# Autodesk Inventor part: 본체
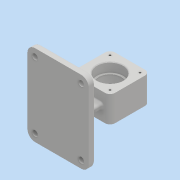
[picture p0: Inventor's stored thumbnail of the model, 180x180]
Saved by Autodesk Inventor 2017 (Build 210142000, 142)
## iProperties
Part Number: 본체
Material: 일반
Document SubType Name: Modeling
Designer: 222
Density: 1 g/cm^3
Appearance: 기본값
Author: 222
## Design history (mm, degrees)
sketch "스케치1"
  geometry: L1 (-32, -32)-(32, -32); L2 (32, -32)-(32, 32); L3 (32, 32)-(-32, 32); L4 (-32, 32)-(-32, -32); L5 (-32, -32)-(32, 32); L6 (32, -32)-(-32, 32); 1 further point
  constraints: 12 end point, 2 midpoint, 2 parallel, 1 horizontal, 1 perpendicular
  dimensions: "d0" = 64 distance of L3.end L2.end; "d1" = 64 distance of L2.end L1.end
extrude "돌출1" new body sketch "스케치1" stored distance "d2" = 42; taper "d3" = 0 deg
sketch "스케치2"
  geometry: C1 r 18 at (0, 0); 1 further point
  constraints: 1 centre point, 1 coincident
  dimensions: "d4" = 36 diameter of C1
extrude "돌출2" cut sketch "스케치2" stored distance "d5" = 42; taper "d6" = 0 deg
hole "구멍1" diameter "d9" = 42; stored, may be unused: countersink angle "d13" = 90 deg, drill point angle "d15" = 0 deg; dims "d7" = 10, "d8" = 10, "d10" = 6, "d11" = 4, "d12" = 2, "d14" = 15
hole "구멍2" diameter "d18" = 42; stored, may be unused: countersink angle "d22" = 90 deg, drill point angle "d24" = 0 deg; dims "d16" = 10, "d17" = 10, "d19" = 6, "d20" = 4, "d21" = 2, "d23" = 15
fillet "모깎기1" dims "d25" = 8
sketch "스케치3"
  geometry: L1 (-24, -24)-(24, -24); L2 (24, -24)-(24, 24); L3 (24, 24)-(-24, 24); L4 (-24, 24)-(-24, -24); L5 (-24, -24)-(24, 24); L6 (24, -24)-(-24, 24); 5 further points
  constraints: 12 end point, 4 coincident, 2 midpoint, 2 parallel, 1 horizontal, 1 perpendicular
  dimensions: "d26" = 48 distance of L3.end L2.end; "d27" = 48 distance of L2.end L1.end
hole "구멍3" sketch "스케치3" at (-24, 24), (24, 24), (-24, -24), (24, -24) diameter "d28" = 3.242; stored, may be unused: countersink angle "d32" = 90 deg, drill point angle "d34" = 118 deg; dims "d29" = 8, "d30" = 4, "d31" = 2, "d33" = 10
sketch "스케치4"
  geometry: L1 (-62, -60)-(36, -60); L2 (36, -60)-(36, -70); L3 (36, -70)-(-62, -70); L4 (-62, -70)-(-62, -60); 1 further point
  constraints: 8 end point, 2 parallel, 1 horizontal, 1 perpendicular
  dimensions: "d35" = 70 distance from line of L3 point (0, 0); "d36" = 10 distance of L1.end L2.end; "d37" = 98 distance of L2.end L3.end; "d38" = 62 distance from line of L4 point (0, 0)
extrude "돌출3" join sketch "스케치4" stored distance "d39" = 130; taper "d40" = 0 deg
sketch "스케치5"
  geometry: L1 (58, 48)-(66, 48); L2 (66, 48)-(66, 82); L3 (66, 82)-(58, 82); L4 (58, 82)-(58, 48); L5 (58, 48)-(66, 82); L6 (66, 48)-(58, 82); L7 (42, 61)-(82, 61); L8 (82, 61)-(82, 69); L9 (82, 69)-(42, 69); L10 (42, 69)-(42, 61); L11 (42, 61)-(82, 69); L12 (82, 61)-(42, 69); L13 (98, 130)-(0, 130) reference; L14 (0, 0)-(0, 130) reference; 4 further points
  constraints: 24 end point, 6 midpoint, 4 parallel, 2 horizontal, 2 perpendicular
  dimensions: "d45" = 8 distance of L3.end L2.end; "d46" = 34 distance of L2.end L1.end; "d47" = 40 distance of L9.end L8.end; "d48" = 8 distance of L8.end L7.end; "d49" = 65 distance from line of L13 point (62, 65); "d50" = 62 distance from line of L14 point (62, 65)
extrude "돌출4" join sketch "스케치5" stored distance "d51" = 130; taper "d52" = 0 deg
fillet "모깎기2" dims "d53" = 12, "d54" = 12
sketch "스케치6"
  geometry: L1 (0, -130)-(74, -130) reference; L2 (-12, -118)-(-12, -12) reference; L3 (74, 0)-(0, 0) reference; L4 (86, -118)-(86, -12) reference; A1 r 12 centre (74, -118) between (74, -130) and (86, -118) reference; A2 r 12 centre (0, -118) between (-12, -118) and (0, -130) reference; A3 r 12 centre (0, -12) between (0, 0) and (-12, -12) reference; A4 r 12 centre (74, -12) between (86, -12) and (74, 0) reference; 5 further points
  constraints: 4 coincident
hole "구멍4" sketch "스케치6" at (0, -118), (0, -12), (74, -12), (74, -118) diameter "d55" = 9; stored, may be unused: countersink angle "d59" = 90 deg, drill point angle "d61" = 0 deg; dims "d56" = 8, "d57" = 4, "d58" = 2, "d60" = 10
fillet "모깎기3" dims "d62" = 3
fillet "모깎기4" dims "d63" = 3
fillet "모깎기5" dims "d64" = 0.3
chamfer "모따기1" distance "d65" = 1; stored, may be unused: second distance "d66" = 2, angle "d67" = 45 deg
sketch "스케치7"
  geometry: L1 (74, 3)-(0, 3) reference; L2 (-12, -9)-(-12, -115) reference; 2 further points
  constraints: 1 other
  dimensions: "d68" = 65 distance from line of L1 point (-2, -62); "d69" = 10 distance from line of L2 point (-2, -62)
feature "엠보싱1" sketch "스케치7" dims "d70" = 0.5, "d71" = 0
node "솔리드1"
mirror "미러1"
node "투영된 루프1"
